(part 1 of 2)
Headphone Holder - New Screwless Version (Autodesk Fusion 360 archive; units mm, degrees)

design "Headphone Holder" references "Basic Mounting", "IKEA SKÅDIS"
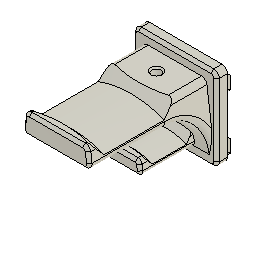
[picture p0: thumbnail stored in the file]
component_insert "Component Insert"
sketch "Sketch1" plane through (0, -5.4, 0) normal (0, -1, 0) x axis (1, 0, 0)
  line L1 (36.4, 44.9) -> (36.4, 35.1)
  line L2 (43.6, 35.1) -> (43.6, 44.9)
  line L3 (-43.6, 44.9) -> (-43.6, 35.1)
  line L4 (-36.4, 35.1) -> (-36.4, 44.9)
  line L5 (3.6, -44.9) -> (3.6, -35.1)
  line L6 (-3.6, -35.1) -> (-3.6, -44.9)
  line L7 (36.4, 4.9) -> (36.4, -4.9)
  line L8 (43.6, -4.9) -> (43.6, 4.9)
  line L9 (-43.6, 4.9) -> (-43.6, -4.9)
  line L10 (-36.4, -4.9) -> (-36.4, 4.9)
  line L11 (23.6, 15.1) -> (23.6, 24.9)
  line L12 (16.4, 24.9) -> (16.4, 15.1)
  line L13 (-16.4, -24.9) -> (-16.4, -15.1)
  line L14 (-23.6, -15.1) -> (-23.6, -24.9)
  line L15 (-16.4, 15.1) -> (-16.4, 24.9)
  line L16 (-23.6, 24.9) -> (-23.6, 15.1)
  line L17 (50, 52.5) -> (50, -52.5)
  line L18 (-50, 52.5) -> (50, 52.5)
  line L19 (-50, -52.5) -> (-50, 52.5)
  line L20 (50, -52.5) -> (-50, -52.5)
  line L21 (23.6, -24.9) -> (23.6, -15.1)
  line L22 (16.4, -15.1) -> (16.4, -24.9)
  line L23 (-3.6, 4.9) -> (-3.6, -4.9)
  line L24 (3.6, -4.9) -> (3.6, 4.9)
  line L25 (-36.4, -44.9) -> (-36.4, -35.1)
  line L26 (-43.6, -35.1) -> (-43.6, -44.9)
  line L27 (43.6, -44.9) -> (43.6, -35.1)
  line L28 (36.4, -35.1) -> (36.4, -44.9)
  line L29 (-3.6, 44.9) -> (-3.6, 35.1)
  line L30 (3.6, 35.1) -> (3.6, 44.9)
  line L31 (30.5, 30.5) -> (-30.5, 30.5)
  line L32 (30.5, -30.5) -> (30.5, 30.5)
  line L33 (-30.5, -30.5) -> (30.5, -30.5)
  line L34 (-30.5, 30.5) -> (-30.5, -30.5)
  line L35 (30.5, -30.5) -> (-30.5, 30.5)
  line L36 (36.4, 44.9) -> (36.4, 35.1)
  line L37 (43.6, 35.1) -> (43.6, 44.9)
  line L38 (-43.6, 44.9) -> (-43.6, 35.1)
  line L39 (-36.4, 35.1) -> (-36.4, 44.9)
  line L40 (3.6, -44.9) -> (3.6, -35.1)
  line L41 (-3.6, -35.1) -> (-3.6, -44.9)
  line L42 (36.4, 4.9) -> (36.4, -4.9)
  line L43 (43.6, -4.9) -> (43.6, 4.9)
  line L44 (-43.6, 4.9) -> (-43.6, -4.9)
  line L45 (-36.4, -4.9) -> (-36.4, 4.9)
  line L46 (23.6, 15.1) -> (23.6, 24.9)
  line L47 (16.4, 24.9) -> (16.4, 15.1)
  line L48 (-16.4, -24.9) -> (-16.4, -15.1)
  line L49 (-23.6, -15.1) -> (-23.6, -24.9)
  line L50 (-16.4, 15.1) -> (-16.4, 24.9)
  line L51 (-23.6, 24.9) -> (-23.6, 15.1)
  line L52 (50, 52.5) -> (50, -52.5)
  line L53 (-50, 52.5) -> (50, 52.5)
  line L54 (-50, -52.5) -> (-50, 52.5)
  line L55 (50, -52.5) -> (-50, -52.5)
  line L56 (23.6, -24.9) -> (23.6, -15.1)
  line L57 (16.4, -15.1) -> (16.4, -24.9)
  line L58 (-3.6, 4.9) -> (-3.6, -4.9)
  line L59 (3.6, -4.9) -> (3.6, 4.9)
  line L60 (-36.4, -44.9) -> (-36.4, -35.1)
  line L61 (-43.6, -35.1) -> (-43.6, -44.9)
  line L62 (43.6, -44.9) -> (43.6, -35.1)
  line L63 (36.4, -35.1) -> (36.4, -44.9)
  line L64 (-3.6, 44.9) -> (-3.6, 35.1)
  line L65 (3.6, 35.1) -> (3.6, 44.9)
  line L66 (36.4, 44.9) -> (36.4, 35.1)
  line L67 (43.6, 35.1) -> (43.6, 44.9)
  line L68 (-43.6, 44.9) -> (-43.6, 35.1)
  line L69 (-36.4, 35.1) -> (-36.4, 44.9)
  line L70 (3.6, -44.9) -> (3.6, -35.1)
  line L71 (-3.6, -35.1) -> (-3.6, -44.9)
  line L72 (36.4, 4.9) -> (36.4, -4.9)
  line L73 (43.6, -4.9) -> (43.6, 4.9)
  line L74 (-43.6, 4.9) -> (-43.6, -4.9)
  line L75 (-36.4, -4.9) -> (-36.4, 4.9)
  line L76 (23.6, 15.1) -> (23.6, 24.9)
  line L77 (16.4, 24.9) -> (16.4, 15.1)
  line L78 (-16.4, -24.9) -> (-16.4, -15.1)
  line L79 (-23.6, -15.1) -> (-23.6, -24.9)
  line L80 (-16.4, 15.1) -> (-16.4, 24.9)
  line L81 (-23.6, 24.9) -> (-23.6, 15.1)
  line L82 (50, 52.5) -> (50, -52.5)
  line L83 (-50, 52.5) -> (50, 52.5)
  line L84 (-50, -52.5) -> (-50, 52.5)
  line L85 (50, -52.5) -> (-50, -52.5)
  line L86 (23.6, -24.9) -> (23.6, -15.1)
  line L87 (16.4, -15.1) -> (16.4, -24.9)
  line L88 (-3.6, 4.9) -> (-3.6, -4.9)
  line L89 (3.6, -4.9) -> (3.6, 4.9)
  line L90 (-36.4, -44.9) -> (-36.4, -35.1)
  line L91 (-43.6, -35.1) -> (-43.6, -44.9)
  line L92 (43.6, -44.9) -> (43.6, -35.1)
  line L93 (36.4, -35.1) -> (36.4, -44.9)
  line L94 (-3.6, 44.9) -> (-3.6, 35.1)
  line L95 (3.6, 35.1) -> (3.6, 44.9)
  arc A1 centre (40, 35.1) radius 3.6 clockwise from (43.6, 35.1) to (36.4, 35.1)
  arc A2 centre (40, 44.9) radius 3.6 clockwise from (36.4, 44.9) to (43.6, 44.9)
  arc A3 centre (-40, 35.1) radius 3.6 clockwise from (-36.4, 35.1) to (-43.6, 35.1)
  arc A4 centre (-40, 44.9) radius 3.6 clockwise from (-43.6, 44.9) to (-36.4, 44.9)
  arc A5 centre (0, -35.1) radius 3.6 clockwise from (-3.6, -35.1) to (3.6, -35.1)
  arc A6 centre (0, -44.9) radius 3.6 clockwise from (3.6, -44.9) to (-3.6, -44.9)
  arc A7 centre (40, -4.9) radius 3.6 clockwise from (43.6, -4.9) to (36.4, -4.9)
  arc A8 centre (40, 4.9) radius 3.6 clockwise from (36.4, 4.9) to (43.6, 4.9)
  arc A9 centre (-40, -4.9) radius 3.6 clockwise from (-36.4, -4.9) to (-43.6, -4.9)
  arc A10 centre (-40, 4.9) radius 3.6 clockwise from (-43.6, 4.9) to (-36.4, 4.9)
  arc A11 centre (20, 15.1) radius 3.6 clockwise from (23.6, 15.1) to (16.4, 15.1)
  arc A12 centre (20, 24.9) radius 3.6 clockwise from (16.4, 24.9) to (23.6, 24.9)
  arc A13 centre (-20, -15.1) radius 3.6 clockwise from (-23.6, -15.1) to (-16.4, -15.1)
  arc A14 centre (-20, -24.9) radius 3.6 clockwise from (-16.4, -24.9) to (-23.6, -24.9)
  arc A15 centre (-20, 24.9) radius 3.6 clockwise from (-23.6, 24.9) to (-16.4, 24.9)
  arc A16 centre (-20, 15.1) radius 3.6 clockwise from (-16.4, 15.1) to (-23.6, 15.1)
  arc A17 centre (20, -15.1) radius 3.6 clockwise from (16.4, -15.1) to (23.6, -15.1)
  arc A18 centre (20, -24.9) radius 3.6 clockwise from (23.6, -24.9) to (16.4, -24.9)
  arc A19 centre (0, -4.9) radius 3.6 clockwise from (3.6, -4.9) to (-3.6, -4.9)
  arc A20 centre (0, 4.9) radius 3.6 clockwise from (-3.6, 4.9) to (3.6, 4.9)
  arc A21 centre (-40, -35.1) radius 3.6 clockwise from (-43.6, -35.1) to (-36.4, -35.1)
  arc A22 centre (-40, -44.9) radius 3.6 clockwise from (-36.4, -44.9) to (-43.6, -44.9)
  arc A23 centre (40, -35.1) radius 3.6 clockwise from (36.4, -35.1) to (43.6, -35.1)
  arc A24 centre (40, -44.9) radius 3.6 clockwise from (43.6, -44.9) to (36.4, -44.9)
  arc A25 centre (0, 35.1) radius 3.6 clockwise from (3.6, 35.1) to (-3.6, 35.1)
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  point P1 (0, 0)
  horizontal L31
  vertical L32
  horizontal L33
  vertical L34
  midpoint P1 L35
  equal L31 L34
  dimension "d27_1" distance A15 L31 = 2
extrude "Extrude1" new body sketch "Sketch1" profile of L11 A11 L12 A12 A13 L13 A14 L14 A15 L15 A16 L16 A17 L21 A18 L22 A19 L23 A20 L24 L31 L32 L33 L34 along normal blind 8 named "d31_1"
fillet "Fillet1" radius 4 named "d34_1"
sketch "Sketch2" plane through (0, -5.4, 0) normal (0, 1, 0) x axis (-1, 0, 0)
  line L1 (26.5, -30.5) -> (-26.5, -30.5)
  line L2 (30.5, 26.5) -> (30.5, -26.5)
  line L3 (-26.5, 30.5) -> (26.5, 30.5)
  line L4 (-30.5, -26.5) -> (-30.5, 26.5)
  line L5 (-22.4, 17.5) -> (-22.4, 15.1)
  line L6 (-17.6, 17.5) -> (-22.4, 17.5)
  line L7 (-17.6, 15.1) -> (-17.6, 17.5)
  arc A1 centre (-26.5, -26.5) radius 4 clockwise from (-26.5, -30.5) to (-30.5, -26.5)
  arc A2 centre (26.5, -26.5) radius 4 clockwise from (30.5, -26.5) to (26.5, -30.5)
  arc A3 centre (26.5, 26.5) radius 4 clockwise from (26.5, 30.5) to (30.5, 26.5)
  arc A4 centre (-26.5, 26.5) radius 4 clockwise from (-30.5, 26.5) to (-26.5, 30.5)
  arc A5 centre (-20, 15.1) radius 2.4 clockwise from (-17.6, 15.1) to (-22.4, 15.1)
  arc A6 centre (-20, 24.9) radius 2.6 clockwise from (-22.6, 24.9) to (-17.4, 24.9)
  arc A7 centre (-20, 15.1) radius 2.6 clockwise from (-17.4, 15.1) to (-22.6, 15.1)
  point P14 (-20, 15.1)
  point P24 (-20, 15.1)
  coincident P14 P24
  tangent A5 L5
  parallel L4 L5
  perpendicular L5 L6
  tangent A5 L7
  perpendicular L6 L7
  tangent A5 L6
  dimension "d38_1" distance A5 A7 = 0.2
extrude "Extrude2" add sketch "Sketch2" profile of A5 L5 L6 L7 along normal blind 5.4 named "d39_1"
sketch "Sketch3" plane through (0, 0, 0) normal (0, 1, 0) x axis (-1, 0, 0)
  line L1 (-17.6, 17.5) -> (-17.6, 15.1)
  line L2 (-22.4, 17.5) -> (-17.6, 17.5)
  line L3 (-22.4, 15.1) -> (-22.4, 17.5)
  line L4 (-22.4, 17.5) -> (-17.6, 17.5)
  line L5 (-22.4, 7.7) -> (-22.4, 17.5)
  line L6 (-17.6, 17.5) -> (-17.6, 7.7)
  line L7 (-17.4, 15.1) -> (-17.4, 24.9)
  arc A1 centre (-20, 15.1) radius 2.4 clockwise from (-17.6, 15.1) to (-22.4, 15.1)
  arc A2 centre (-20, 7.7) radius 2.4 clockwise from (-17.6, 7.7) to (-22.4, 7.7)
  point P5 (-17.6, 17.5)
  point P7 (-17.6, 17.5)
  point P6 (-22.4, 17.5)
  point P8 (-22.4, 17.5)
  point P9 (-22.4, 7.7)
  point P12 (-22.4, 7.7)
  horizontal L4
  vertical L5
  vertical L6
  coincident P5 P7
  coincident P6 P8
  equal L6 L7
  tangent L6 A2
  tangent L5 A2
  coincident P9 P12
extrude "Extrude3" add sketch "Sketch3" profile of A1 L1 L2 L3 L4 L5 L6 A2 along normal blind 5 named "d41_1"
fillet "Fillet2" radius 2.5 named "d44_1"
sketch "Sketch4" plane through (22.4, 0, 0) normal (1, 0, 0) x axis (0, 0, -1)
  line L1 (-17.5, -2.9) -> (-17.5, 2.5)
  line L2 (-15.1, -5.4) -> (-20, -5.4)
  line L3 (-15.1, 0) -> (-15.1, -5.4)
  line L4 (-7.7, 0) -> (-15.1, 0)
  line L5 (-7.7, 5) -> (-7.7, 0)
  line L6 (-15, 5) -> (-7.7, 5)
  line L7 (-4.7, 0.8038) -> (-7.7, 0)
  line L8 (-4.7, 0) -> (-4.7, 0.8038)
  line L9 (-7.7, 0) -> (-4.7, 0)
  arc A1 centre (-15, 2.5) radius 2.5 clockwise from (-17.5, 2.5) to (-15, 5)
  arc A2 centre (-20, -2.9) radius 2.5 clockwise from (-17.5, -2.9) to (-20, -5.4)
  point P10 (-7.7, 0)
  point P12 (-7.7, 0)
  point P14 (-4.7, 0)
  coincident P10 P12
  perpendicular L4 L8
  perpendicular L5 L9
  dimension "d45_1" angle L7 L9 = 15
  dimension "d46_1" distance P12 P14 = 3
extrude "Extrude4" cut sketch "Sketch4" profile of L7 L8 L9 no distance stored
rectangular_pattern "R-Pattern1" uSpaceDistance -40 named "d50_1" vSpaceDistance -40 named "d51_1"
sketch "Sketch5" plane through (0, -5.4, 0) normal (0, 1, 0) x axis (-1, 0, 0)
  line L1 (22.4, 20) -> (17.6, 20)
  line L2 (22.4, 15.1) -> (22.4, 20)
  line L3 (17.6, 20) -> (17.6, 15.1)
  line L4 (-17.6, 15.1) -> (-17.6, 20)
  line L5 (-22.4, 20) -> (-22.4, 15.1)
  line L6 (-17.6, 20) -> (-22.4, 20)
  line L7 (22.4, -20) -> (17.6, -20)
  line L8 (22.4, -24.9) -> (22.4, -20)
  line L9 (17.6, -20) -> (17.6, -24.9)
  line L10 (-17.6, -20) -> (-22.4, -20)
  line L11 (-17.6, -24.9) -> (-17.6, -20)
  line L12 (-22.4, -20) -> (-22.4, -24.9)
  line L13 (26.5, -30.5) -> (-26.5, -30.5)
  line L14 (30.5, 26.5) -> (30.5, -26.5)
  line L15 (-26.5, 30.5) -> (26.5, 30.5)
  line L16 (-30.5, -26.5) -> (-30.5, 26.5)
  line L17 (22.4, 27.3) -> (-22.4, 27.3)
  line L18 (22.4, -27.3) -> (22.4, 27.3)
  line L19 (-22.4, -27.3) -> (22.4, -27.3)
  line L20 (-22.4, 27.3) -> (-22.4, -27.3)
  line L21 (22.4, -27.3) -> (-22.4, 27.3)
  line L22 (-22.4, -27.3) -> (22.4, 27.3)
  arc A1 centre (20, 15.1) radius 2.4 clockwise from (22.4, 15.1) to (17.6, 15.1)
  arc A2 centre (-20, 15.1) radius 2.4 clockwise from (-17.6, 15.1) to (-22.4, 15.1)
  arc A3 centre (20, -24.9) radius 2.4 clockwise from (22.4, -24.9) to (17.6, -24.9)
  arc A4 centre (-20, -24.9) radius 2.4 clockwise from (-17.6, -24.9) to (-22.4, -24.9)
  arc A5 centre (-26.5, -26.5) radius 4 clockwise from (-26.5, -30.5) to (-30.5, -26.5)
  arc A6 centre (26.5, -26.5) radius 4 clockwise from (30.5, -26.5) to (26.5, -30.5)
  arc A7 centre (26.5, 26.5) radius 4 clockwise from (26.5, 30.5) to (30.5, 26.5)
  arc A8 centre (-26.5, 26.5) radius 4 clockwise from (-30.5, 26.5) to (-26.5, 30.5)
  point P38 (0, 0)
  point P1 (0, 0)
  horizontal L17
  perpendicular L17 L18
  parallel L17 L19
  parallel L18 L20
  coincident L21 P38
  coincident L22 P38
  coincident P1 P38
  tangent A3 L19
  tangent A3 L18
extrude "Extrude9" new body sketch "Sketch5" profile of L1 L2 A1 L3 L4 A2 L5 L6 L7 L8 A3 L9 L10 L11 A4 L12 L17 L18 L19 L20 against normal blind 5 bodies "Part Cutter"
sketch "Sketch11" plane through (0, -5.4, 0) normal (0, 1, 0) x axis (-1, 0, 0)
  line L1 (22.4, -27.3) -> (-22.4, -27.3)
  line L2 (22.4, 27.3) -> (22.4, -27.3)
  line L3 (-22.4, 27.3) -> (22.4, 27.3)
  line L4 (-22.4, -27.3) -> (-22.4, 27.3)
  circle C1 centre (0, 0) radius 45
  point P1 (0, 0)
  point P6 (0, 0)
  coincident P1 P6
  dimension "d150" diameter C1 = 90
extrude "Extrude10" add sketch "Sketch11" along normal blind 15
sketch "Sketch7" plane through (0, 0, 27.3) normal (0, 0, 1) x axis (1, 0, 0)
  line L1 (-22.4, -5.4) -> (22.4, -5.4)
  line L2 (-22.4, -10.4) -> (-22.4, -5.4)
  line L3 (22.4, -10.4) -> (-22.4, -10.4)
  line L4 (22.4, -5.4) -> (22.4, -10.4)
  line L5 (-27.4, -10.4) -> (-22.4, -5.4)
  line L6 (-22.4, -10.4) -> (-27.4, -10.4)
  line L7 (27.4, -10.4) -> (22.4, -5.4)
  line L8 (22.4, -10.4) -> (27.4, -10.4)
  point P3 (-22.4, -5.4)
  point P6 (-22.4, -5.4)
  point P4 (-22.4, -10.4)
  point P8 (-22.4, -10.4)
  point P2 (22.4, -5.4)
  point P9 (22.4, -5.4)
  point P5 (22.4, -10.4)
  point P11 (22.4, -10.4)
  coincident P3 P6
  coincident P4 P8
  coincident P2 P9
  coincident P5 P11
  perpendicular L4 L8
  perpendicular L2 L6
  equal L2 L6
  equal L4 L8
extrude "Extrude11" add sketch "Sketch7" profile of L2 L4 L5 L6 L7 L8 to an object
combine "Combine1" bodies "Mount Left Hook"
work_plane "WorkPlane1" AlongDistance 0
work_plane "WorkPlane2" AlongDistance 0
split "Split1" bodies "Mount Right Hook", "Mount Middle Part"
extrude "Extrude2" cut of existing geometry blind -0.2
offset_faces "OffsetFaces1" distance -0.2
sketch "Sketch3" plane through (17.6, 0, 0) normal (-1, 0, 0) x axis (0, 0, 1)
  line L1 (17.5, 2.5) -> (17.5, -2.9)
  line L2 (7.7, 5) -> (15, 5)
  line L3 (7.7, 0) -> (7.7, 5)
  line L4 (15.1, 0) -> (7.7, 0)
  line L5 (15.1, -5.4) -> (15.1, 0)
  line L6 (-20, -5.4) -> (15.1, -5.4)
  line L7 (-22.5, 2.5) -> (-22.5, -2.9)
  line L8 (-32.3, 5) -> (-25, 5)
  line L9 (-32.3, 0) -> (-32.3, 5)
  line L10 (-24.9, 0) -> (-32.3, 0)
  line L11 (-24.9, -5.4) -> (-24.9, 0)
  line L12 (-27.3, -5.4) -> (-24.9, -5.4)
  line L13 (-27.3, -10.4) -> (-27.3, -5.4)
  line L14 (27.3, -10.4) -> (-27.3, -10.4)
  line L15 (27.3, -5.4) -> (27.3, -10.4)
  line L16 (20, -5.4) -> (27.3, -5.4)
  line L17 (-9.5, -7.9) -> (-12, -5.4)
  line L18 (9.5, -7.9) -> (-9.5, -7.9)
  line L19 (12, -5.4) -> (9.5, -7.9)
  line L20 (0, -7.9) -> (0, -10.4)
  arc A1 centre (15, 2.5) radius 2.5 clockwise from (15, 5) to (17.5, 2.5)
  arc A2 centre (-20, -2.9) radius 2.5 clockwise from (-20, -5.4) to (-22.5, -2.9)
  arc A3 centre (-25, 2.5) radius 2.5 clockwise from (-25, 5) to (-22.5, 2.5)
  arc A4 centre (20, -2.9) radius 2.5 clockwise from (20, -5.4) to (17.5, -2.9)
  point P26 (-12, -5.4)
  point P29 (12, -5.4)
  point P30 (0, -10.4)
  point P31 (0, -7.9)
  point P27 (-9.5, -7.9)
  coincident L6 P26
  parallel L6 L18
  coincident L6 P29
  midpoint L14 P30
  midpoint L18 P31
  vertical L20
  dimension "d163" angle L17 L18 = 135
  dimension "d164" angle L18 L19 = 135
  dimension "d165" distance P26 P29 = 24
  dimension "d166" distance P26 P27 = 2.5
extrude "Extrude3" cut sketch "Sketch3" profile of L6 L17 L18 L19 no distance stored
sketch "Sketch4" plane through (17.4, 0, 0) normal (1, 0, 0) x axis (0, 0, -1)
  line L1 (-27.3, -5.4) -> (27.3, -5.4)
  line L2 (-27.3, -10.4) -> (-27.3, -5.4)
  line L3 (27.3, -10.4) -> (-27.3, -10.4)
  line L4 (27.3, -5.4) -> (27.3, -10.4)
  line L5 (-12, -5.4) -> (-9.5, -7.9)
  line L6 (-9.5, -7.9) -> (9.5, -7.9)
  line L7 (9.5, -7.9) -> (12, -5.4)
  line L8 (9.4172, -7.7) -> (11.8586, -5.2586)
  line L9 (-9.4172, -7.7) -> (9.4172, -7.7)
  line L10 (-11.8586, -5.2586) -> (-9.4172, -7.7)
  line L11 (-9.5, -7.9) -> (9.5, -7.9)
  line L12 (9.5, -7.9) -> (12, -5.4)
  line L13 (-12, -5.4) -> (-9.5, -7.9)
  dimension "d168" = 0.2
extrude "Extrude4" add sketch "Sketch4" profile of L1 L8 L9 L10 to an object Side2Offset 0
sketch "Sketch8" plane through (0, -5.4, 0) normal (0, 1, 0) x axis (-1, 0, 0)
  line L1 (-17.4, -27.3) -> (-17.4, -11.7172)
  line L2 (17.4, -27.3) -> (-17.4, -27.3)
  line L3 (17.4, -11.7172) -> (17.4, -27.3)
  line L4 (22.4, -11.7172) -> (17.4, -11.7172)
  line L5 (22.4, 11.7172) -> (22.4, -11.7172)
  line L6 (17.4, 11.7172) -> (22.4, 11.7172)
  line L7 (17.4, 27.3) -> (17.4, 11.7172)
  line L8 (-17.4, 27.3) -> (17.4, 27.3)
  line L9 (-17.4, 11.7172) -> (-17.4, 27.3)
  line L10 (-22.4, 11.7172) -> (-17.4, 11.7172)
  line L11 (-22.4, -11.7172) -> (-22.4, 11.7172)
  line L12 (-17.4, -11.7172) -> (-22.4, -11.7172)
  line L13 (-22.4, 0) -> (22.4, 0)
  line L14 (0, 27.3) -> (0, -27.3)
  circle C1 centre (13.4, 0) radius 1.6
  circle C2 centre (13.4, 0) radius 3
  circle C3 centre (-13.4, 0) radius 1.6
  circle C4 centre (-13.4, 0) radius 3
  point P14 (22.4, 0)
  point P15 (-22.4, 0)
  point P16 (13.4, 0)
  point P18 (0, -27.3)
  point P19 (0, 27.3)
  midpoint L5 P14
  midpoint L11 P15
  coincident L13 P16
  concentric C1 C2
  midpoint L2 P18
  midpoint L8 P19
  symmetric C1 L14 C3
  symmetric C2 L14 C4
  dimension "d205" diameter C1 = 3.2
  dimension "d206" diameter C2 = 6
  dimension "d208" distance L5 C2 = 6
extrude "Extrude9" cut sketch "Sketch8" profile of C1 C3 no distance stored
extrude "Extrude6" cut sketch "Sketch8" profile of C1 C2 C3 C4 against normal blind 3
sketch "Sketch7" plane through (0, -8.4, 0) normal (0, 1, 0) x axis (-1, 0, 0)
  line L1 (-10.8623, 1.6) -> (-15.9377, 1.6)
  line L2 (-10.8623, -1.6) -> (-15.9377, -1.6)
  line L3 (-15, -1.6) -> (-15, 1.6)
  line L4 (-11.8, -1.6) -> (-11.8, 1.6)
  circle C1 centre (-13.4, 0) radius 1.6
  circle C2 centre (-13.4, 0) radius 3
  point P3 (-15.9377, 1.6)
  point P4 (-10.8623, 1.6)
  point P5 (-15.9377, -1.6)
  point P6 (-10.8623, -1.6)
  point P7 (-15, 1.6)
  point P8 (-15, -1.6)
  point P9 (-11.8, 1.6)
  point P10 (-11.8, -1.6)
  coincident C2 P3
  coincident C2 P4
  horizontal L1
  coincident C2 P5
  coincident C2 P6
  parallel L1 L2
  coincident L1 P7
  coincident L2 P8
  perpendicular L1 L3
  coincident L1 P9
  perpendicular L1 L4
  tangent C1 L1
  tangent C1 L2
  tangent C1 L3
  tangent C1 L4
  coincident L2 P10
extrude "Extrude10" cut sketch "Sketch7" profile of C1 L1 L2 L3 L4 against normal blind 0.4
extrude "Extrude11" cut sketch "Sketch7" profile of C2 L1 L2 L3 L4 against normal blind 0.2
mirror "Mirror2" mirrorStitchTolerance 0.1
combine "Combine3" bodies "Part Cutter"
offset_faces "OffsetFaces2" distance -0.2
sketch "Sketch11" plane through (0, -10.6, 0) normal (0, 1, 0) x axis (-1, 0, 0)
  line L1 (27.8828, -27.5) -> (-27.8828, -27.5)
  line L2 (27.8828, 27.5) -> (27.8828, -27.5)
  line L3 (-27.8828, 27.5) -> (27.8828, 27.5)
  line L4 (-27.8828, -27.5) -> (-27.8828, 27.5)
  circle C1 centre (13.4, 0) radius 1.6
  circle C2 centre (-13.4, 0) radius 1.6
  circle C3 centre (13.4, 0) radius 1.25
  circle C4 centre (-13.4, 0) radius 1.25
  concentric C1 C3
  concentric C2 C4
  equal C3 C4
  dimension "d220" diameter C3 = 2.5
extrude "Extrude13" cut sketch "Sketch11" profile of C3 C4 against normal blind 2
copy_paste_bodies "CopyPasteBodies3"
component_from_bodies "Body->Comp3"
sketch "Sketch1" plane through (0, -13.4, 0) normal (0, -1, 0) x axis (1, 0, 0)
  line L1 (25, 8.5) -> (-25, 8.5)
  line L2 (23.0252, 23.5) -> (25, 8.5)
  line L3 (-23.0252, 23.5) -> (23.0252, 23.5)
  line L4 (-25, 8.5) -> (-23.0252, 23.5)
  line L5 (0, 23.5) -> (0, 8.5)
  line L6 (-26.5, 30.5) -> (26.5, 30.5)
  line L7 (30.5, 26.5) -> (30.5, -26.5)
  line L8 (30.5, 26.5) -> (30.5, -26.5)
  line L9 (-26.5, 30.5) -> (26.5, 30.5)
  line L10 (-30.5, -26.5) -> (-30.5, 26.5)
  line L11 (26.5, -30.5) -> (-26.5, -30.5)
  line L12 (30.5, 26.5) -> (30.5, -26.5)
  line L13 (-26.5, 30.5) -> (26.5, 30.5)
  line L14 (-30.5, -26.5) -> (-30.5, 26.5)
  line L15 (26.5, -30.5) -> (-26.5, -30.5)
  arc A1 centre (0, -48.5) radius 67 clockwise from (-24.2832, 13.9446) to (24.2832, 13.9446)
  arc A2 centre (26.5, -26.5) radius 4 clockwise from (30.5, -26.5) to (26.5, -30.5)
  arc A3 centre (26.5, 26.5) radius 4 clockwise from (26.5, 30.5) to (30.5, 26.5)
  arc A4 centre (-26.5, 26.5) radius 4 clockwise from (-30.5, 26.5) to (-26.5, 30.5)
  arc A5 centre (-26.5, -26.5) radius 4 clockwise from (-26.5, -30.5) to (-30.5, -26.5)
  arc A6 centre (26.5, -26.5) radius 4 clockwise from (30.5, -26.5) to (26.5, -30.5)
  arc A7 centre (26.5, 26.5) radius 4 clockwise from (26.5, 30.5) to (30.5, 26.5)
  arc A8 centre (-26.5, 26.5) radius 4 clockwise from (-30.5, 26.5) to (-26.5, 30.5)
  arc A9 centre (-26.5, -26.5) radius 4 clockwise from (-26.5, -30.5) to (-30.5, -26.5)
  point P5 (0, 8.5)
  point P6 (0, 23.5)
  point P8 (24.2832, 13.9446)
  point P7 (0, -48.5)
  point P9 (-24.2832, 13.9446)
  point P11 (25, 8.5)
  point P2 (25, 8.5)
  point P1 (0, 0)
  point P10 (-25, 8.5)
  midpoint L1 P5
  midpoint L3 P6
  perpendicular L1 L5
  coincident L2 P8
  coincident L5 P7
  coincident L4 P9
  coincident L2 P11
  coincident P2 P11
  coincident P1 L5
  vertical L5
  dimension "d52" angle L2 L4 = 15
  dimension "d53" distance L1 L3 = 15
  dimension "d68" distance A1 L6 = 12
  dimension "d69" distance L3 A1 = 5
  dimension "d70" radius A1 = 67
  dimension "d99" distance P10 P11 = 50
extrude "Extrude6" add sketch "Sketch1" profile of L1 L2 L3 L4 along normal blind 87
fillet "Fillet14" radius 32
fillet "Fillet16" radius 4
chamfer "Chamfer6" distance 2
sketch "Sketch2" plane through (0, 0, 0) normal (1, 0, 0) x axis (0, 0, -1)
  line L1 (-18.5, -45.4) -> (-18.5, -89.4)
  line L2 (-28.5, -35.4) -> (-18.5, -45.4)
  line L3 (-28.5, -99.4) -> (-28.5, -35.4)
  line L4 (-18.5, -89.4) -> (-28.5, -99.4)
  line L5 (-18.5, -67.4) -> (-28.5, -67.4)
  line L6 (-23.5, -13.4) -> (-23.5, -98.4)
  line L7 (-23.5, -98.4) -> (-23.5, -13.4)
  point P2 (-18.5, -89.4)
  point P6 (-18.5, -89.4)
  point P7 (-23.5, -94.4)
  point P8 (-28.5, -67.4)
  point P9 (-18.5, -67.4)
  point P10 (-23.5, -40.4)
  point P3 (-18.5, -45.4)
  point P11 (-23.5, -98.4)
  coincident P2 P6
  coincident L4 P7
  midpoint L4 P7
  midpoint L3 P8
  midpoint L1 P9
  perpendicular L1 L5
  midpoint L2 P10
  coincident P7 L6
  parallel L3 L7
  parallel L1 L7
  dimension "d118" angle L2 L4 = 90
  dimension "d119" distance P2 P3 = 44
  dimension "d227" distance P7 P11 = 4
  dimension "d228" distance P2 P11 = 5
sketch "Sketch3" plane through (0, 0, 0) normal (0, 1, 0) x axis (1, 0, 0)
  line L1 (0, 48.5) -> (0, 0)
  circle C1 centre (0, 48.5) radius 67
  point P2 (0, -18.5)
  point P1 (0, 0)
  point P4 (0, 0)
  point P3 (0, 48.5)
  point P5 (0, 48.5)
  coincident P2 C1
  coincident P1 P4
  coincident P3 P5
  vertical L1
  dimension "d110" diameter C1 = 134 (= "( 67 * 2 ) * 1 mm")
sweep "Sweep1" sketch "Sketch2" TwistAngle 0 TaperAngle 0
extrude "Extrude1" of existing geometry blind -8
delete_face "DeleteFace1"
delete_face "DeleteFace2"
sketch "Sketch12" plane through (0, 0, 27.5) normal (0, 0, -1) x axis (-1, 0, 0)
  line L1 (-22.6828, -5.4) -> (22.6828, -5.4)
  line L2 (-27.8828, -10.6) -> (-22.6828, -5.4)
  line L3 (27.8828, -10.6) -> (-27.8828, -10.6)
  line L4 (22.6828, -5.4) -> (27.8828, -10.6)
  line L5 (6, -6.4) -> (-6, -6.4)
  line L6 (6, -8.4) -> (6, -6.4)
  line L7 (-6, -8.4) -> (6, -8.4)
  line L8 (-6, -6.4) -> (-6, -8.4)
  line L9 (0, -6.4) -> (0, -5.4)
  point P10 (0, -5.4)
  point P11 (0, -6.4)
  point P8 (6, -8.4)
  point P9 (-6, -8.4)
  point P6 (-6, -6.4)
  horizontal L5
  vertical L6
  horizontal L7
  vertical L8
  midpoint L1 P10
  midpoint L5 P11
  perpendicular L5 L9
  dimension "d256" distance P8 P9 = 12
  dimension "d257" distance P6 P9 = 2
  dimension "d258" distance L1 L5 = 1
extrude "Extrude2" cut sketch "Sketch12" profile of L5 L6 L7 L8 against normal blind 1.2
mirror "Mirror1" mirrorStitchTolerance 0.1
copy_paste_bodies "CopyPasteBodies4"
component_from_bodies "Body->Comp4"
sketch "Sketch1" plane through (0, -13.4, 0) normal (0, -1, 0) x axis (1, 0, 0)
  line L1 (-13.6835, -13.5) -> (-15, -23.5)
  line L2 (13.6835, -13.5) -> (-13.6835, -13.5)
  line L3 (15, -23.5) -> (13.6835, -13.5)
  line L4 (0, -13.5) -> (0, 0)
  line L5 (25.1784, -23.5) -> (20.4389, 8.5)
  line L6 (-20.4389, 8.5) -> (20.4389, 8.5)
  line L7 (-20.4389, 8.5) -> (-25.1784, -23.5)
  line L8 (25.1784, -23.5) -> (-25.1784, -23.5)
  line L9 (15, -23.5) -> (-15, -23.5)
  line L10 (0, -23.5) -> (0, -13.5)
  line L11 (30.5, 26.5) -> (30.5, -26.5)
  line L12 (-26.5, 30.5) -> (26.5, 30.5)
  line L13 (-30.5, -26.5) -> (-30.5, 26.5)
  line L14 (26.5, -30.5) -> (-26.5, -30.5)
  line L15 (-23.4831, 20.0221) -> (-26.9729, -6.4855)
  line L16 (19.5173, 23.5) -> (-19.5173, 23.5)
  line L17 (26.9729, -6.4855) -> (23.4831, 20.0221)
  curve K1 (25.1784, -23.5) -> (26.9729, -6.4855)
  line L18 (-25.1784, -23.5) -> (25.1784, -23.5)
  curve K2 (-26.9729, -6.4855) -> (-25.1784, -23.5)
  line L19 (28.5, 26.5) -> (28.5, -26.5)
  line L20 (-26.5, 28.5) -> (26.5, 28.5)
  line L21 (-28.5, -26.5) -> (-28.5, 26.5)
  line L22 (26.5, -28.5) -> (-26.5, -28.5)
  arc A1 centre (26.5, -26.5) radius 4 clockwise from (30.5, -26.5) to (26.5, -30.5)
  arc A2 centre (26.5, 26.5) radius 4 clockwise from (26.5, 30.5) to (30.5, 26.5)
  arc A3 centre (-26.5, 26.5) radius 4 clockwise from (-30.5, 26.5) to (-26.5, 30.5)
  arc A4 centre (-26.5, -26.5) radius 4 clockwise from (-26.5, -30.5) to (-30.5, -26.5)
  arc A5 centre (-19.5173, 19.5) radius 4 clockwise from (-23.4831, 20.0221) to (-19.5173, 23.5)
  arc A6 centre (19.5173, 19.5) radius 4 clockwise from (19.5173, 23.5) to (23.4831, 20.0221)
  arc A7 centre (26.5, -26.5) radius 2 clockwise from (28.5, -26.5) to (26.5, -28.5)
  arc A8 centre (26.5, 26.5) radius 2 clockwise from (26.5, 28.5) to (28.5, 26.5)
  arc A9 centre (-26.5, 26.5) radius 2 clockwise from (-28.5, 26.5) to (-26.5, 28.5)
  arc A10 centre (-26.5, -26.5) radius 2 clockwise from (-26.5, -28.5) to (-28.5, -26.5)
  point P1 (0, 0)
  point P6 (0, 0)
  point P7 (0, -13.5)
  point P2 (-15, -23.5)
  point P5 (15, -23.5)
  point P12 (0, -23.5)
  coincident P1 P6
  midpoint L2 P7
  vertical L4
  coincident P2 L8
  coincident P5 L8
  equal L1 L3
  midpoint L9 P12
  vertical L10
  dimension "d145" angle L1 L3 = 15
  dimension "d146" distance P2 P5 = 30
  dimension "d147" distance L2 L9 = 10
extrude "Extrude8" new body sketch "Sketch1" profile of L1 L2 L3 L8 L9 L18 along normal blind 40 bodies "Cable Holder"
fillet "Fillet2" radius 3
chamfer "Chamfer1" distance 2
sketch "Sketch2" plane through (0, 0, 0) normal (1, 0, 0) x axis (0, 0, -1)
  line L1 (16.5, -44.4) -> (16.5, -19.4)
  line L2 (10.5, -50.4) -> (16.5, -44.4)
  line L3 (10.5, -13.4) -> (16.5, -19.4)
  line L4 (10.5, -50.4) -> (10.5, -13.4)
  line L5 (13.5, -13.4) -> (13.5, -51.4)
  line L6 (13.5, -51.4) -> (13.5, -13.4)
  point P5 (13.5, -47.4)
  point P4 (10.5, -50.4)
  point P8 (10.5, -50.4)
  point P9 (13.5, -16.4)
  point P10 (13.5, -51.4)
  point P2 (16.5, -19.4)
  point P3 (16.5, -44.4)
  coincident L2 P5
  vertical L1
  coincident P4 P8
  coincident L3 P9
  vertical L4
  midpoint L2 P5
  midpoint L3 P9
  coincident P5 L5
  dimension "d130" distance L1 P10 = 3
  dimension "d139" angle L2 L4 = 45
  dimension "d141" angle L3 L4 = 45
  dimension "d143" distance P2 P3 = 25
  dimension "d244" distance P5 P10 = 4
sketch "Sketch3" plane through (0, -53.4, 0) normal (0, -1, 0) x axis (1, 0, 0)
  line L1 (0, -54) -> (0, -16.5)
  line L2 (-12.5706, -20.3695) -> (-12.044, -16.3695)
  line L3 (11.5792, -21.5) -> (-11.5792, -21.5)
  line L4 (12.044, -16.3695) -> (12.5706, -20.3695)
  line L5 (-11.0525, -15.5) -> (11.0525, -15.5)
  circle C1 centre (0, -54) radius 37.5
  arc A1 centre (-11.0525, -16.5) radius 1 clockwise from (-12.044, -16.3695) to (-11.0525, -15.5)
  arc A2 centre (-11.5792, -20.5) radius 1 clockwise from (-11.5792, -21.5) to (-12.5706, -20.3695)
  arc A3 centre (11.5792, -20.5) radius 1 clockwise from (12.5706, -20.3695) to (11.5792, -21.5)
  arc A4 centre (11.0525, -16.5) radius 1 clockwise from (11.0525, -15.5) to (12.044, -16.3695)
  point P3 (0, -16.5)
  point P4 (0, -16.5)
  point P2 (0, -54)
  point P5 (0, -54)
  coincident C1 P3
  coincident P3 P4
  coincident P2 P5
  vertical L1
  dimension "d132" diameter C1 = 75
sweep "Sweep1" sketch "Sketch2" TwistAngle 0 TaperAngle 0
combine "Combine1" bodies "Cable Holder"
delete_face "DeleteFace3"
copy_paste_bodies "CopyPasteBodies5"
component_from_bodies "Body->Comp6"
sketch "Sketch1" plane through (0, 0, 23.5) normal (0, 0, 1) x axis (1, 0, 0)
  curve K1 (19.5173, -37.8016) -> (-19.5173, -37.8016)
  line L1 (19.5173, -13.4) -> (19.5173, -37.8016)
  line L2 (-19.5173, -13.4) -> (19.5173, -13.4)
  line L3 (-19.5173, -37.8016) -> (-19.5173, -13.4)
  line L4 (0, -40.4) -> (0, -13.4)
  circle C1 centre (0, -26.9) radius 3.35
  point P6 (0, -13.4)
  point P7 (0, -40.4)
  point P8 (0, -26.9)
  midpoint L2 P6
  coincident K1 P7
  perpendicular L2 L4
  midpoint L4 P8
  dimension "d252" diameter C1 = 6.7
extrude "Extrude1" cut sketch "Sketch1" profile of C1 against normal blind 25
chamfer "Chamfer1" distance 1
remove_instance "RemoveInstance1"
external_derived "Sketch8" bodies "Left Pegs", "Right Pegs", "Lock Plate", "Left Peg", "Right Peg", "Middle Peg"
derived_instance "DerivedInstance1"
derived_instance "DerivedInstance2"
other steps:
derived_base_feature "Sketch8" bodies "Left Pegs", "Right Pegs", "Lock Plate"
derived_base_feature "Sketch13" bodies "Left Peg", "Right Peg", "Lock Plate", "Middle Peg"
base_feature "Base Feature1" bodies "Headphone Holder + Cable Hook + Adapter Hole"
base_feature "Base Feature3" bodies "Base Plate"
base_feature "Base Feature4" bodies "Headphone Holder", "Headphone Holder + Cable Hook"
base_feature "Base Feature5" bodies "Headphone Holder + Cable Hook", "Headphone Holder + Cable Hook + Adapter Hole"
base_feature "Base Feature1" bodies "Base Plate", "Headphone Holder"
base_feature "Base Feature1" bodies "Headphone Holder + Cable Hook"
create_component "CreateComponent2"
create_component "CreateComponent5"
create_component "CreateComponent8"
create_component "CreateComponent9"
remove_body "RemoveBody3"
create_component "CreateComponent10"
remove_body "RemoveBody4"
create_component "CreateComponent12"
remove_body "RemoveBody6"
create_component "CreateComponent13"
create_component "CreateComponent14"
named bodies: "Base Plate", "Part Cutter", "Mount Left Hook", "Mount Right Hook", "Mount Middle Part", "Headphone Holder", "Headphone Holder + Cable Hook", "Cable Holder", "Headphone Holder + Cable Hook + Adapter Hole", "Left Pegs", "Right Pegs", "Lock Plate", "Left Peg", "Right Peg", "Middle Peg"

design "Basic Mounting" references "IKEA SKÅDIS"
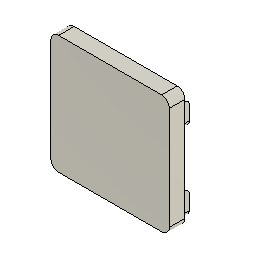
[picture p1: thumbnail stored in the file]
component_insert "Component Insert"
sketch "Sketch1" plane through (0, -5.4, 0) normal (0, -1, 0) x axis (1, 0, 0)
  line L1 (36.4, 44.9) -> (36.4, 35.1)
  line L2 (43.6, 35.1) -> (43.6, 44.9)
  line L3 (-43.6, 44.9) -> (-43.6, 35.1)
  line L4 (-36.4, 35.1) -> (-36.4, 44.9)
  line L5 (3.6, -44.9) -> (3.6, -35.1)
  line L6 (-3.6, -35.1) -> (-3.6, -44.9)
  line L7 (36.4, 4.9) -> (36.4, -4.9)
  line L8 (43.6, -4.9) -> (43.6, 4.9)
  line L9 (-43.6, 4.9) -> (-43.6, -4.9)
  line L10 (-36.4, -4.9) -> (-36.4, 4.9)
  line L11 (23.6, 15.1) -> (23.6, 24.9)
  line L12 (16.4, 24.9) -> (16.4, 15.1)
  line L13 (-16.4, -24.9) -> (-16.4, -15.1)
  line L14 (-23.6, -15.1) -> (-23.6, -24.9)
  line L15 (-16.4, 15.1) -> (-16.4, 24.9)
  line L16 (-23.6, 24.9) -> (-23.6, 15.1)
  line L17 (50, 52.5) -> (50, -52.5)
  line L18 (-50, 52.5) -> (50, 52.5)
  line L19 (-50, -52.5) -> (-50, 52.5)
  line L20 (50, -52.5) -> (-50, -52.5)
  line L21 (23.6, -24.9) -> (23.6, -15.1)
  line L22 (16.4, -15.1) -> (16.4, -24.9)
  line L23 (-3.6, 4.9) -> (-3.6, -4.9)
  line L24 (3.6, -4.9) -> (3.6, 4.9)
  line L25 (-36.4, -44.9) -> (-36.4, -35.1)
  line L26 (-43.6, -35.1) -> (-43.6, -44.9)
  line L27 (43.6, -44.9) -> (43.6, -35.1)
  line L28 (36.4, -35.1) -> (36.4, -44.9)
  line L29 (-3.6, 44.9) -> (-3.6, 35.1)
  line L30 (3.6, 35.1) -> (3.6, 44.9)
  line L31 (30.5, 30.5) -> (-30.5, 30.5)
  line L32 (30.5, -30.5) -> (30.5, 30.5)
  line L33 (-30.5, -30.5) -> (30.5, -30.5)
  line L34 (-30.5, 30.5) -> (-30.5, -30.5)
  line L35 (30.5, -30.5) -> (-30.5, 30.5)
  line L36 (36.4, 44.9) -> (36.4, 35.1)
  line L37 (43.6, 35.1) -> (43.6, 44.9)
  line L38 (-43.6, 44.9) -> (-43.6, 35.1)
  line L39 (-36.4, 35.1) -> (-36.4, 44.9)
  line L40 (3.6, -44.9) -> (3.6, -35.1)
  line L41 (-3.6, -35.1) -> (-3.6, -44.9)
  line L42 (36.4, 4.9) -> (36.4, -4.9)
  line L43 (43.6, -4.9) -> (43.6, 4.9)
  line L44 (-43.6, 4.9) -> (-43.6, -4.9)
  line L45 (-36.4, -4.9) -> (-36.4, 4.9)
  line L46 (23.6, 15.1) -> (23.6, 24.9)
  line L47 (16.4, 24.9) -> (16.4, 15.1)
  line L48 (-16.4, -24.9) -> (-16.4, -15.1)
  line L49 (-23.6, -15.1) -> (-23.6, -24.9)
  line L50 (-16.4, 15.1) -> (-16.4, 24.9)
  line L51 (-23.6, 24.9) -> (-23.6, 15.1)
  line L52 (50, 52.5) -> (50, -52.5)
  line L53 (-50, 52.5) -> (50, 52.5)
  line L54 (-50, -52.5) -> (-50, 52.5)
  line L55 (50, -52.5) -> (-50, -52.5)
  line L56 (23.6, -24.9) -> (23.6, -15.1)
  line L57 (16.4, -15.1) -> (16.4, -24.9)
  line L58 (-3.6, 4.9) -> (-3.6, -4.9)
  line L59 (3.6, -4.9) -> (3.6, 4.9)
  line L60 (-36.4, -44.9) -> (-36.4, -35.1)
  line L61 (-43.6, -35.1) -> (-43.6, -44.9)
  line L62 (43.6, -44.9) -> (43.6, -35.1)
  line L63 (36.4, -35.1) -> (36.4, -44.9)
  line L64 (-3.6, 44.9) -> (-3.6, 35.1)
  line L65 (3.6, 35.1) -> (3.6, 44.9)
  arc A1 centre (40, 35.1) radius 3.6 clockwise from (43.6, 35.1) to (36.4, 35.1)
  arc A2 centre (40, 44.9) radius 3.6 clockwise from (36.4, 44.9) to (43.6, 44.9)
  arc A3 centre (-40, 35.1) radius 3.6 clockwise from (-36.4, 35.1) to (-43.6, 35.1)
  arc A4 centre (-40, 44.9) radius 3.6 clockwise from (-43.6, 44.9) to (-36.4, 44.9)
  arc A5 centre (0, -35.1) radius 3.6 clockwise from (-3.6, -35.1) to (3.6, -35.1)
  arc A6 centre (0, -44.9) radius 3.6 clockwise from (3.6, -44.9) to (-3.6, -44.9)
  arc A7 centre (40, -4.9) radius 3.6 clockwise from (43.6, -4.9) to (36.4, -4.9)
  arc A8 centre (40, 4.9) radius 3.6 clockwise from (36.4, 4.9) to (43.6, 4.9)
  arc A9 centre (-40, -4.9) radius 3.6 clockwise from (-36.4, -4.9) to (-43.6, -4.9)
  arc A10 centre (-40, 4.9) radius 3.6 clockwise from (-43.6, 4.9) to (-36.4, 4.9)
  arc A11 centre (20, 15.1) radius 3.6 clockwise from (23.6, 15.1) to (16.4, 15.1)
  arc A12 centre (20, 24.9) radius 3.6 clockwise from (16.4, 24.9) to (23.6, 24.9)
  arc A13 centre (-20, -15.1) radius 3.6 clockwise from (-23.6, -15.1) to (-16.4, -15.1)
  arc A14 centre (-20, -24.9) radius 3.6 clockwise from (-16.4, -24.9) to (-23.6, -24.9)
  arc A15 centre (-20, 24.9) radius 3.6 clockwise from (-23.6, 24.9) to (-16.4, 24.9)
  arc A16 centre (-20, 15.1) radius 3.6 clockwise from (-16.4, 15.1) to (-23.6, 15.1)
  arc A17 centre (20, -15.1) radius 3.6 clockwise from (16.4, -15.1) to (23.6, -15.1)
  arc A18 centre (20, -24.9) radius 3.6 clockwise from (23.6, -24.9) to (16.4, -24.9)
  arc A19 centre (0, -4.9) radius 3.6 clockwise from (3.6, -4.9) to (-3.6, -4.9)
  arc A20 centre (0, 4.9) radius 3.6 clockwise from (-3.6, 4.9) to (3.6, 4.9)
  arc A21 centre (-40, -35.1) radius 3.6 clockwise from (-43.6, -35.1) to (-36.4, -35.1)
  arc A22 centre (-40, -44.9) radius 3.6 clockwise from (-36.4, -44.9) to (-43.6, -44.9)
  arc A23 centre (40, -35.1) radius 3.6 clockwise from (36.4, -35.1) to (43.6, -35.1)
  arc A24 centre (40, -44.9) radius 3.6 clockwise from (43.6, -44.9) to (36.4, -44.9)
  arc A25 centre (0, 35.1) radius 3.6 clockwise from (3.6, 35.1) to (-3.6, 35.1)
  arc A26 centre (0, 44.9) radius 3.6 clockwise from (-3.6, 44.9) to (3.6, 44.9)
  arc A27 centre (40, 35.1) radius 3.6 clockwise from (43.6, 35.1) to (36.4, 35.1)
  arc A28 centre (40, 44.9) radius 3.6 clockwise from (36.4, 44.9) to (43.6, 44.9)
  arc A29 centre (-40, 35.1) radius 3.6 clockwise from (-36.4, 35.1) to (-43.6, 35.1)
  arc A30 centre (-40, 44.9) radius 3.6 clockwise from (-43.6, 44.9) to (-36.4, 44.9)
  arc A31 centre (0, -35.1) radius 3.6 clockwise from (-3.6, -35.1) to (3.6, -35.1)
  arc A32 centre (0, -44.9) radius 3.6 clockwise from (3.6, -44.9) to (-3.6, -44.9)
  arc A33 centre (40, -4.9) radius 3.6 clockwise from (43.6, -4.9) to (36.4, -4.9)
  arc A34 centre (40, 4.9) radius 3.6 clockwise from (36.4, 4.9) to (43.6, 4.9)
  arc A35 centre (-40, -4.9) radius 3.6 clockwise from (-36.4, -4.9) to (-43.6, -4.9)
  arc A36 centre (-40, 4.9) radius 3.6 clockwise from (-43.6, 4.9) to (-36.4, 4.9)
  arc A37 centre (20, 15.1) radius 3.6 clockwise from (23.6, 15.1) to (16.4, 15.1)
  arc A38 centre (20, 24.9) radius 3.6 clockwise from (16.4, 24.9) to (23.6, 24.9)
  arc A39 centre (-20, -15.1) radius 3.6 clockwise from (-23.6, -15.1) to (-16.4, -15.1)
  arc A40 centre (-20, -24.9) radius 3.6 clockwise from (-16.4, -24.9) to (-23.6, -24.9)
  arc A41 centre (-20, 24.9) radius 3.6 clockwise from (-23.6, 24.9) to (-16.4, 24.9)
  arc A42 centre (-20, 15.1) radius 3.6 clockwise from (-16.4, 15.1) to (-23.6, 15.1)
  arc A43 centre (20, -15.1) radius 3.6 clockwise from (16.4, -15.1) to (23.6, -15.1)
  arc A44 centre (20, -24.9) radius 3.6 clockwise from (23.6, -24.9) to (16.4, -24.9)
  arc A45 centre (0, -4.9) radius 3.6 clockwise from (3.6, -4.9) to (-3.6, -4.9)
  arc A46 centre (0, 4.9) radius 3.6 clockwise from (-3.6, 4.9) to (3.6, 4.9)
  arc A47 centre (-40, -35.1) radius 3.6 clockwise from (-43.6, -35.1) to (-36.4, -35.1)
  arc A48 centre (-40, -44.9) radius 3.6 clockwise from (-36.4, -44.9) to (-43.6, -44.9)
  arc A49 centre (40, -35.1) radius 3.6 clockwise from (36.4, -35.1) to (43.6, -35.1)
  arc A50 centre (40, -44.9) radius 3.6 clockwise from (43.6, -44.9) to (36.4, -44.9)
  arc A51 centre (0, 35.1) radius 3.6 clockwise from (3.6, 35.1) to (-3.6, 35.1)
  arc A52 centre (0, 44.9) radius 3.6 clockwise from (-3.6, 44.9) to (3.6, 44.9)
  point P1 (0, 0)
  horizontal L31
  vertical L32
  horizontal L33
  vertical L34
  midpoint P1 L35
  equal L31 L34
  dimension "d27" distance A15 L31 = 2
extrude "Extrude1" new body sketch "Sketch1" profile of L11 A11 L12 A12 A13 L13 A14 L14 A15 L15 A16 L16 A17 L21 A18 L22 A19 L23 A20 L24 L31 L32 L33 L34 along normal blind 8
fillet "Fillet1" radius 4
sketch "Sketch2" plane through (0, -5.4, 0) normal (0, 1, 0) x axis (-1, 0, 0)
  line L1 (26.5, -30.5) -> (-26.5, -30.5)
  line L2 (30.5, 26.5) -> (30.5, -26.5)
  line L3 (-26.5, 30.5) -> (26.5, 30.5)
  line L4 (-30.5, -26.5) -> (-30.5, 26.5)
  line L5 (-22.4, 17.5) -> (-22.4, 15.1)
  line L6 (-17.6, 17.5) -> (-22.4, 17.5)
  line L7 (-17.6, 15.1) -> (-17.6, 17.5)
  arc A1 centre (-26.5, -26.5) radius 4 clockwise from (-26.5, -30.5) to (-30.5, -26.5)
  arc A2 centre (26.5, -26.5) radius 4 clockwise from (30.5, -26.5) to (26.5, -30.5)
  arc A3 centre (26.5, 26.5) radius 4 clockwise from (26.5, 30.5) to (30.5, 26.5)
  arc A4 centre (-26.5, 26.5) radius 4 clockwise from (-30.5, 26.5) to (-26.5, 30.5)
  arc A5 centre (-20, 15.1) radius 2.4 clockwise from (-17.6, 15.1) to (-22.4, 15.1)
  arc A6 centre (-20, 24.9) radius 2.6 clockwise from (-22.6, 24.9) to (-17.4, 24.9)
  arc A7 centre (-20, 15.1) radius 2.6 clockwise from (-17.4, 15.1) to (-22.6, 15.1)
  point P14 (-20, 15.1)
  point P24 (-20, 15.1)
  coincident P14 P24
  tangent A5 L5
  parallel L4 L5
  perpendicular L5 L6
  tangent A5 L7
  perpendicular L6 L7
  tangent A5 L6
  dimension "d38" distance A5 A7 = 0.2
extrude "Extrude2" add sketch "Sketch2" profile of A5 L5 L6 L7 along normal blind 5.4
sketch "Sketch3" plane through (0, 0, 0) normal (0, 1, 0) x axis (-1, 0, 0)
  line L1 (-17.6, 17.5) -> (-17.6, 15.1)
  line L2 (-22.4, 17.5) -> (-17.6, 17.5)
  line L3 (-22.4, 15.1) -> (-22.4, 17.5)
  line L4 (-22.4, 17.5) -> (-17.6, 17.5)
  line L5 (-22.4, 7.7) -> (-22.4, 17.5)
  line L6 (-17.6, 17.5) -> (-17.6, 7.7)
  line L7 (-17.4, 15.1) -> (-17.4, 24.9)
  arc A1 centre (-20, 15.1) radius 2.4 clockwise from (-17.6, 15.1) to (-22.4, 15.1)
  arc A2 centre (-20, 7.7) radius 2.4 clockwise from (-17.6, 7.7) to (-22.4, 7.7)
  point P5 (-17.6, 17.5)
  point P7 (-17.6, 17.5)
  point P6 (-22.4, 17.5)
  point P8 (-22.4, 17.5)
  point P9 (-22.4, 7.7)
  point P12 (-22.4, 7.7)
  horizontal L4
  vertical L5
  vertical L6
  coincident P5 P7
  coincident P6 P8
  equal L6 L7
  tangent L6 A2
  tangent L5 A2
  coincident P9 P12
extrude "Extrude3" add sketch "Sketch3" profile of A1 L1 L2 L3 L4 L5 L6 A2 along normal blind 5
fillet "Fillet2" radius 2.5
sketch "Sketch4" plane through (22.4, 0, 0) normal (1, 0, 0) x axis (0, 0, -1)
  line L1 (-17.5, -2.9) -> (-17.5, 2.5)
  line L2 (-15.1, -5.4) -> (-20, -5.4)
  line L3 (-15.1, 0) -> (-15.1, -5.4)
  line L4 (-7.7, 0) -> (-15.1, 0)
  line L5 (-7.7, 5) -> (-7.7, 0)
  line L6 (-15, 5) -> (-7.7, 5)
  line L7 (-4.7, 0.8038) -> (-7.7, 0)
  line L8 (-4.7, 0) -> (-4.7, 0.8038)
  line L9 (-7.7, 0) -> (-4.7, 0)
  arc A1 centre (-15, 2.5) radius 2.5 clockwise from (-17.5, 2.5) to (-15, 5)
  arc A2 centre (-20, -2.9) radius 2.5 clockwise from (-17.5, -2.9) to (-20, -5.4)
  point P10 (-7.7, 0)
  point P12 (-7.7, 0)
  point P14 (-4.7, 0)
  coincident P10 P12
  perpendicular L4 L8
  perpendicular L5 L9
  dimension "d45" angle L7 L9 = 15
  dimension "d46" distance P12 P14 = 3
extrude "Extrude4" cut sketch "Sketch4" profile of L7 L8 L9 no distance stored
rectangular_pattern "R-Pattern1" uSpaceDistance -40 vSpaceDistance -40
sketch "Sketch5" plane through (0, -5.4, 0) normal (0, 1, 0) x axis (-1, 0, 0)
  line L1 (22.4, 20) -> (17.6, 20)
  line L2 (22.4, 15.1) -> (22.4, 20)
  line L3 (17.6, 20) -> (17.6, 15.1)
  line L4 (-17.6, 15.1) -> (-17.6, 20)
  line L5 (-22.4, 20) -> (-22.4, 15.1)
  line L6 (-17.6, 20) -> (-22.4, 20)
  line L7 (22.4, -20) -> (17.6, -20)
  line L8 (22.4, -24.9) -> (22.4, -20)
  line L9 (17.6, -20) -> (17.6, -24.9)
  line L10 (-17.6, -20) -> (-22.4, -20)
  line L11 (-17.6, -24.9) -> (-17.6, -20)
  line L12 (-22.4, -20) -> (-22.4, -24.9)
  line L13 (26.5, -30.5) -> (-26.5, -30.5)
  line L14 (30.5, 26.5) -> (30.5, -26.5)
  line L15 (-26.5, 30.5) -> (26.5, 30.5)
  line L16 (-30.5, -26.5) -> (-30.5, 26.5)
  line L17 (22.4, 27.3) -> (-22.4, 27.3)
  line L18 (22.4, -27.3) -> (22.4, 27.3)
  line L19 (-22.4, -27.3) -> (22.4, -27.3)
  line L20 (-22.4, 27.3) -> (-22.4, -27.3)
  line L21 (22.4, -27.3) -> (-22.4, 27.3)
  line L22 (-22.4, -27.3) -> (22.4, 27.3)
  arc A1 centre (20, 15.1) radius 2.4 clockwise from (22.4, 15.1) to (17.6, 15.1)
  arc A2 centre (-20, 15.1) radius 2.4 clockwise from (-17.6, 15.1) to (-22.4, 15.1)
  arc A3 centre (20, -24.9) radius 2.4 clockwise from (22.4, -24.9) to (17.6, -24.9)
  arc A4 centre (-20, -24.9) radius 2.4 clockwise from (-17.6, -24.9) to (-22.4, -24.9)
  arc A5 centre (-26.5, -26.5) radius 4 clockwise from (-26.5, -30.5) to (-30.5, -26.5)
  arc A6 centre (26.5, -26.5) radius 4 clockwise from (30.5, -26.5) to (26.5, -30.5)
  arc A7 centre (26.5, 26.5) radius 4 clockwise from (26.5, 30.5) to (30.5, 26.5)
  arc A8 centre (-26.5, 26.5) radius 4 clockwise from (-30.5, 26.5) to (-26.5, 30.5)
  point P38 (0, 0)
  point P1 (0, 0)
  horizontal L17
  perpendicular L17 L18
  parallel L17 L19
  parallel L18 L20
  coincident L21 P38
  coincident L22 P38
  coincident P1 P38
  tangent A3 L19
  tangent A3 L18
extrude "Extrude9" new body sketch "Sketch5" profile of L1 L2 A1 L3 L4 A2 L5 L6 L7 L8 A3 L9 L10 L11 A4 L12 L17 L18 L19 L20 against normal blind 5 bodies "Part Cutter"
sketch "Sketch6" plane through (0, -5.4, 0) normal (0, 1, 0) x axis (-1, 0, 0)
  line L1 (22.4, -27.3) -> (-22.4, -27.3)
  line L2 (22.4, 27.3) -> (22.4, -27.3)
  line L3 (-22.4, 27.3) -> (22.4, 27.3)
  line L4 (-22.4, -27.3) -> (-22.4, 27.3)
  circle C1 centre (0, 0) radius 45
  point P1 (0, 0)
  point P6 (0, 0)
  coincident P1 P6
  dimension "d150" diameter C1 = 90
extrude "Extrude10" add sketch "Sketch6" along normal blind 15
sketch "Sketch7" plane through (0, 0, 27.3) normal (0, 0, 1) x axis (1, 0, 0)
  line L1 (-22.4, -5.4) -> (22.4, -5.4)
  line L2 (-22.4, -10.4) -> (-22.4, -5.4)
  line L3 (22.4, -10.4) -> (-22.4, -10.4)
  line L4 (22.4, -5.4) -> (22.4, -10.4)
  line L5 (-27.4, -10.4) -> (-22.4, -5.4)
  line L6 (-22.4, -10.4) -> (-27.4, -10.4)
  line L7 (27.4, -10.4) -> (22.4, -5.4)
  line L8 (22.4, -10.4) -> (27.4, -10.4)
  point P3 (-22.4, -5.4)
  point P6 (-22.4, -5.4)
  point P4 (-22.4, -10.4)
  point P8 (-22.4, -10.4)
  point P2 (22.4, -5.4)
  point P9 (22.4, -5.4)
  point P5 (22.4, -10.4)
  point P11 (22.4, -10.4)
  coincident P3 P6
  coincident P4 P8
  coincident P2 P9
  coincident P5 P11
  perpendicular L4 L8
  perpendicular L2 L6
  equal L2 L6
  equal L4 L8
extrude "Extrude11" add sketch "Sketch7" profile of L2 L4 L5 L6 L7 L8 to an object
combine "Combine1" bodies "Left Pegs"
work_plane "WorkPlane1" AlongDistance 0
work_plane "WorkPlane2" AlongDistance 0
split "Split1" bodies "Right Pegs"
extrude "Extrude2" cut of existing geometry blind -0.2
offset_faces "OffsetFaces1" distance -0.2
sketch "Sketch8" plane through (17.6, 0, 0) normal (-1, 0, 0) x axis (0, 0, 1)
  line L1 (17.5, 2.5) -> (17.5, -2.9)
  line L2 (7.7, 5) -> (15, 5)
  line L3 (7.7, 0) -> (7.7, 5)
  line L4 (15.1, 0) -> (7.7, 0)
  line L5 (15.1, -5.4) -> (15.1, 0)
  line L6 (-20, -5.4) -> (15.1, -5.4)
  line L7 (-22.5, 2.5) -> (-22.5, -2.9)
  line L8 (-32.3, 5) -> (-25, 5)
  line L9 (-32.3, 0) -> (-32.3, 5)
  line L10 (-24.9, 0) -> (-32.3, 0)
  line L11 (-24.9, -5.4) -> (-24.9, 0)
  line L12 (-27.3, -5.4) -> (-24.9, -5.4)
  line L13 (-27.3, -10.4) -> (-27.3, -5.4)
  line L14 (27.3, -10.4) -> (-27.3, -10.4)
  line L15 (27.3, -5.4) -> (27.3, -10.4)
  line L16 (20, -5.4) -> (27.3, -5.4)
  line L17 (-9.5, -7.9) -> (-12, -5.4)
  line L18 (9.5, -7.9) -> (-9.5, -7.9)
  line L19 (12, -5.4) -> (9.5, -7.9)
  line L20 (0, -7.9) -> (0, -10.4)
  arc A1 centre (15, 2.5) radius 2.5 clockwise from (15, 5) to (17.5, 2.5)
  arc A2 centre (-20, -2.9) radius 2.5 clockwise from (-20, -5.4) to (-22.5, -2.9)
  arc A3 centre (-25, 2.5) radius 2.5 clockwise from (-25, 5) to (-22.5, 2.5)
  arc A4 centre (20, -2.9) radius 2.5 clockwise from (20, -5.4) to (17.5, -2.9)
  point P26 (-12, -5.4)
  point P29 (12, -5.4)
  point P30 (0, -10.4)
  point P31 (0, -7.9)
  point P27 (-9.5, -7.9)
  coincident L6 P26
  parallel L6 L18
  coincident L6 P29
  midpoint L14 P30
  midpoint L18 P31
  vertical L20
  dimension "d163" angle L17 L18 = 135
  dimension "d164" angle L18 L19 = 135
  dimension "d165" distance P26 P29 = 24
  dimension "d166" distance P26 P27 = 2.5
extrude "Extrude3" cut sketch "Sketch8" profile of L6 L17 L18 L19 no distance stored
sketch "Sketch9" plane through (17.4, 0, 0) normal (1, 0, 0) x axis (0, 0, -1)
  line L1 (-27.3, -5.4) -> (27.3, -5.4)
  line L2 (-27.3, -10.4) -> (-27.3, -5.4)
  line L3 (27.3, -10.4) -> (-27.3, -10.4)
  line L4 (27.3, -5.4) -> (27.3, -10.4)
  line L5 (-12, -5.4) -> (-9.5, -7.9)
  line L6 (-9.5, -7.9) -> (9.5, -7.9)
  line L7 (9.5, -7.9) -> (12, -5.4)
  line L8 (9.4172, -7.7) -> (11.8586, -5.2586)
  line L9 (-9.4172, -7.7) -> (9.4172, -7.7)
  line L10 (-11.8586, -5.2586) -> (-9.4172, -7.7)
  line L11 (-9.5, -7.9) -> (9.5, -7.9)
  line L12 (9.5, -7.9) -> (12, -5.4)
  line L13 (-12, -5.4) -> (-9.5, -7.9)
  dimension "d168" = 0.2
extrude "Extrude4" add sketch "Sketch9" profile of L1 L8 L9 L10 to an object Side2Offset 0
sketch "Sketch10" plane through (0, -5.4, 0) normal (0, 1, 0) x axis (-1, 0, 0)
  line L1 (-17.4, -27.3) -> (-17.4, -11.7172)
  line L2 (17.4, -27.3) -> (-17.4, -27.3)
  line L3 (17.4, -11.7172) -> (17.4, -27.3)
  line L4 (22.4, -11.7172) -> (17.4, -11.7172)
  line L5 (22.4, 11.7172) -> (22.4, -11.7172)
  line L6 (17.4, 11.7172) -> (22.4, 11.7172)
  line L7 (17.4, 27.3) -> (17.4, 11.7172)
  line L8 (-17.4, 27.3) -> (17.4, 27.3)
  line L9 (-17.4, 11.7172) -> (-17.4, 27.3)
  line L10 (-22.4, 11.7172) -> (-17.4, 11.7172)
  line L11 (-22.4, -11.7172) -> (-22.4, 11.7172)
  line L12 (-17.4, -11.7172) -> (-22.4, -11.7172)
  line L13 (-22.4, 0) -> (22.4, 0)
  line L14 (0, 27.3) -> (0, -27.3)
  circle C1 centre (13.4, 0) radius 1.6
  circle C2 centre (13.4, 0) radius 3
  circle C3 centre (-13.4, 0) radius 1.6
  circle C4 centre (-13.4, 0) radius 3
  point P14 (22.4, 0)
  point P15 (-22.4, 0)
  point P16 (13.4, 0)
  point P18 (0, -27.3)
  point P19 (0, 27.3)
  midpoint L5 P14
  midpoint L11 P15
  coincident L13 P16
  concentric C1 C2
  midpoint L2 P18
  midpoint L8 P19
  symmetric C1 L14 C3
  symmetric C2 L14 C4
  dimension "d205" diameter C1 = 3.2
  dimension "d206" diameter C2 = 6
  dimension "d208" distance L5 C2 = 6
extrude "Extrude9" cut sketch "Sketch10" profile of C1 C3 no distance stored
extrude "Extrude6" cut sketch "Sketch10" profile of C1 C2 C3 C4 against normal blind 3
sketch "Sketch11" plane through (0, -8.4, 0) normal (0, 1, 0) x axis (-1, 0, 0)
  line L1 (-10.8623, 1.6) -> (-15.9377, 1.6)
  line L2 (-10.8623, -1.6) -> (-15.9377, -1.6)
  line L3 (-15, -1.6) -> (-15, 1.6)
  line L4 (-11.8, -1.6) -> (-11.8, 1.6)
  circle C1 centre (-13.4, 0) radius 1.6
  circle C2 centre (-13.4, 0) radius 3
  point P3 (-15.9377, 1.6)
  point P4 (-10.8623, 1.6)
  point P5 (-15.9377, -1.6)
  point P6 (-10.8623, -1.6)
  point P7 (-15, 1.6)
  point P8 (-15, -1.6)
  point P9 (-11.8, 1.6)
  point P10 (-11.8, -1.6)
  coincident C2 P3
  coincident C2 P4
  horizontal L1
  coincident C2 P5
  coincident C2 P6
  parallel L1 L2
  coincident L1 P7
  coincident L2 P8
  perpendicular L1 L3
  coincident L1 P9
  perpendicular L1 L4
  tangent C1 L1
  tangent C1 L2
  tangent C1 L3
  tangent C1 L4
  coincident L2 P10
extrude "Extrude10" cut sketch "Sketch11" profile of C1 L1 L2 L3 L4 against normal blind 0.4
extrude "Extrude11" cut sketch "Sketch11" profile of C2 L1 L2 L3 L4 against normal blind 0.2
mirror "Mirror2" mirrorStitchTolerance 0.1
offset_faces "OffsetFaces3" distance -0.2
combine "Combine3" bodies "Part Cutter"
offset_faces "OffsetFaces2" distance -0.2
